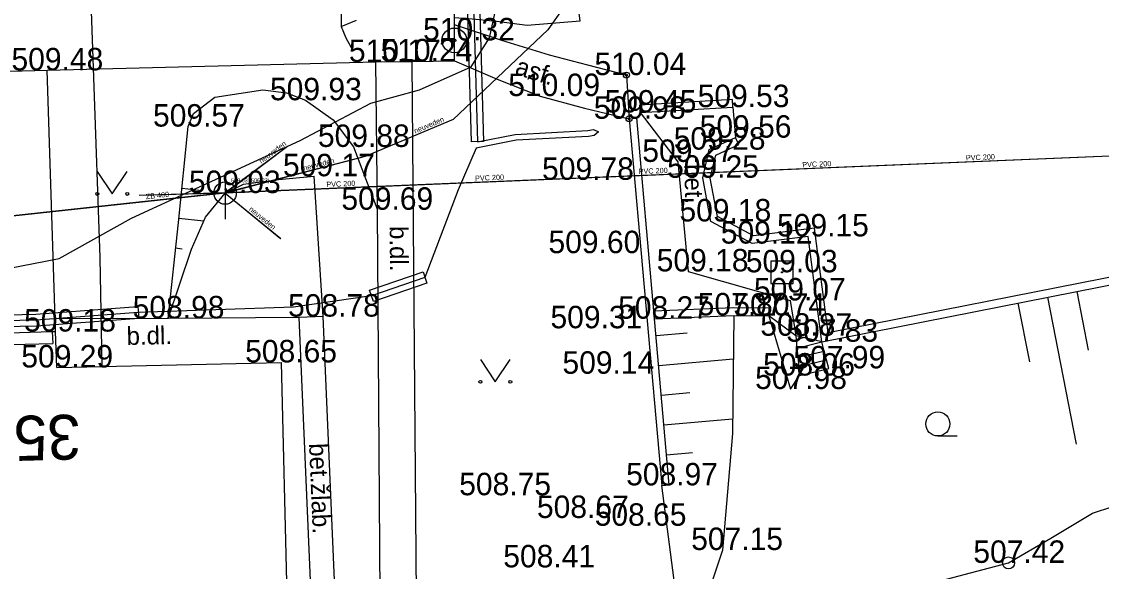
# Model space of a CAD drawing. Extents: x -669642 to -669119, y -1131006 to -1130466.
# Drawn here: x -669449.88 to -669413.8, y -1130563.48 to -1130545.11 of the extents above; entities that cross this region are included whole.
import ezdxf

# ---------------------------------------------------------------- set-up
doc = ezdxf.new("R2010")
doc.units = 0
for name, color, linetype in [('G_Bod_tecka', 7, 'Continuous'), ('G_Bod_vyska', 7, 'Continuous'), ('G_Bodove_pole', 7, 'Continuous'), ('G_Breh_Teren', 7, 'Continuous'), ('G_Budovy_Objekty', 7, 'Continuous'), ('G_Cesty_Schody', 7, 'Continuous'), ('G_Cisla_popisna', 7, 'Continuous'), ('G_Plochy_zpevnene', 7, 'Continuous'), ('G_Ploty', 7, 'Continuous'), ('G_Ploty_vstupy', 7, 'Continuous'), ('G_Popisy_povrchu', 7, 'Continuous'), ('G_Site-kanalizace', 7, 'Continuous'), ('G_Site-Sachty_N', 7, 'Continuous'), ('G_Site-Sloupy', 7, 'Continuous'), ('G_Vyskove_srafy', 7, 'Continuous'), ('G_Z_CHRANICKA-TEPLOVOD_kotovane', 7, 'Continuous'), ('G_Z_ELsilove_podz_kotovane', 7, 'Continuous'), ('G_Z_ELsilove_zrusene', 7, 'Continuous'), ('G_Z_KANAL_podz_kotovane', 7, 'Continuous'), ('G_Z_KANAL_podz_priblizne', 7, 'Continuous'), ('G_Z_PLYNY_podz_geodeticky', 7, 'Continuous'), ('G_Zelen-Znacky', 7, 'Continuous'), ('Vrstva 10', 7, 'Continuous'), ('Vrstva 12', 7, 'Continuous'), ('Vrstva 17', 7, 'Continuous'), ('Vrstva 2', 7, 'Continuous'), ('Vrstva 3', 7, 'Continuous'), ('Vrstva 8', 7, 'Continuous')]:
    doc.layers.add(name, color=color, linetype=linetype)

msp = doc.modelspace()

# ---------------------------------------------------------------- linework, layer by layer
at = {"layer": 'G_Bod_tecka'}
for p, q in [((-669435.42, -1130545.74), (-669435.42, -1130545.74)), ((-669438.04, -1130546.46), (-669438.04, -1130546.46)), ((-669436.84, -1130546.44), (-669436.84, -1130546.44)), ((-669449.03, -1130546.74), (-669449.03, -1130546.74)), ((-669429.67, -1130546.9), (-669429.67, -1130546.9)), ((-669432.55, -1130547.6), (-669432.55, -1130547.6)), ((-669440.39, -1130547.74), (-669440.39, -1130547.74)), ((-669426.11, -1130547.97), (-669426.11, -1130547.97)), ((-669429.58, -1130548.36), (-669429.58, -1130548.36)), ((-669429.21, -1130548.15), (-669429.21, -1130548.15)), ((-669444.31, -1130548.62), (-669444.31, -1130548.62)), ((-669426.02, -1130548.99), (-669426.02, -1130548.99)), ((-669438.79, -1130549.3), (-669438.79, -1130549.3)), ((-669426.9, -1130549.39), (-669426.9, -1130549.39)), ((-669427.95, -1130549.8), (-669427.95, -1130549.8)), ((-669440.1, -1130550.28), (-669440.1, -1130550.28)), ((-669431.3, -1130550.4), (-669431.3, -1130550.4)), ((-669427.12, -1130550.33), (-669427.12, -1130550.33)), ((-669443.08, -1130550.84), (-669443.08, -1130550.84)), ((-669437.99, -1130551.4), (-669437.99, -1130551.4)), ((-669426.85, -1130551.79), (-669426.85, -1130551.79)), ((-669423.6, -1130552.29), (-669423.6, -1130552.29)), ((-669425.47, -1130552.53), (-669425.47, -1130552.53)), ((-669431.05, -1130552.85), (-669431.05, -1130552.85)), ((-669427.61, -1130553.46), (-669427.61, -1130553.46)), ((-669424.47, -1130553.49), (-669424.47, -1130553.49)), ((-669424.2, -1130554.43), (-669424.2, -1130554.43)), ((-669444.98, -1130555.03), (-669444.98, -1130555.03)), ((-669439.8, -1130554.97), (-669439.8, -1130554.97)), ((-669428.76, -1130555.04), (-669428.76, -1130555.04)), ((-669426.08, -1130554.93), (-669426.08, -1130554.93)), ((-669424.91, -1130554.94), (-669424.91, -1130554.94)), ((-669448.75, -1130555.47), (-669448.75, -1130555.47)), ((-669431.08, -1130555.36), (-669431.08, -1130555.36)), ((-669424.01, -1130555.61), (-669424.01, -1130555.61)), ((-669423.14, -1130555.81), (-669423.14, -1130555.81)), ((-669448.7, -1130556.67), (-669448.7, -1130556.67)), ((-669441.21, -1130556.5), (-669441.21, -1130556.5)), ((-669422.91, -1130556.7), (-669422.91, -1130556.7)), ((-669430.76, -1130556.88), (-669430.76, -1130556.88)), ((-669423.88, -1130556.94), (-669423.88, -1130556.94)), ((-669424.19, -1130557.39), (-669424.19, -1130557.39)), ((-669428.49, -1130560.61), (-669428.49, -1130560.61)), ((-669434.07, -1130560.94), (-669434.07, -1130560.94)), ((-669431.46, -1130561.7), (-669431.46, -1130561.7)), ((-669429.53, -1130561.96), (-669429.53, -1130561.96)), ((-669426.46, -1130562.77), (-669426.46, -1130562.77)), ((-669416.9, -1130563.2), (-669416.9, -1130563.2)), ((-669432.66, -1130563.35), (-669432.66, -1130563.35))]:
    msp.add_line(p, q, dxfattribs=at)
at = {"layer": 'G_Bodove_pole'}
for radius in [0.412, 0.05]:
    msp.add_circle((-669435.42, -1130545.74), radius, dxfattribs=at)
at = {"layer": 'G_Breh_Teren'}
for p, q in [((-669439.8, -1130554.97), (-669440.1, -1130550.28)), ((-669424.01, -1130555.61), (-669424.91, -1130554.94)), ((-669424.91, -1130554.94), (-669424.19, -1130557.39)), ((-669424.19, -1130557.39), (-669423.88, -1130556.94))]:
    msp.add_line(p, q, dxfattribs=at)
for points in [[(-669444.98, -1130555.03), (-669444.64, -1130551.82), (-669444.31, -1130548.62), (-669444.14, -1130548.18), (-669443.42, -1130547.64), (-669441.82, -1130547.39), (-669441.03, -1130547.49), (-669440.39, -1130547.74), (-669439.47, -1130548.4), (-669438.79, -1130549.3), (-669438.39, -1130550.35), (-669437.99, -1130551.4)], [(-669444.98, -1130555.03), (-669444.2, -1130552.72), (-669443.74, -1130551.65), (-669443.08, -1130550.84), (-669442.46, -1130550.54), (-669441.3, -1130550.39), (-669440.1, -1130550.28)], [(-669426.08, -1130554.93), (-669426.12, -1130558.88), (-669426.46, -1130562.77), (-669427.04, -1130564.51), (-669427.76, -1130566.22)], [(-669427.76, -1130566.22), (-669425.46, -1130565.53), (-669423.17, -1130564.84), (-669420.03, -1130564.02), (-669416.9, -1130563.2), (-669415.49, -1130562.37), (-669414.09, -1130561.54), (-669413.41, -1130561.32), (-669412.72, -1130561.11)]]:
    msp.add_lwpolyline(points, dxfattribs=at)
at = {"layer": 'G_Budovy_Objekty'}
for p, q in [((-669452.25, -1130555.57), (-669448.86, -1130555.47)), ((-669448.86, -1130555.47), (-669448.84, -1130555.87)), ((-669448.86, -1130555.47), (-669448.75, -1130555.47)), ((-669448.7, -1130556.67), (-669448.75, -1130555.47)), ((-669452.24, -1130555.96), (-669448.84, -1130555.87)), ((-669448.7, -1130556.67), (-669441.21, -1130556.5)), ((-669441.21, -1130556.5), (-669440.93, -1130567.9))]:
    msp.add_line(p, q, dxfattribs=at)
at = {"layer": 'G_Cesty_Schody'}
for p, q in [((-669448.75, -1130555.47), (-669448.76, -1130555.05)), ((-669424.01, -1130555.61), (-669424, -1130555.73)), ((-669423.75, -1130555.67), (-669424.01, -1130555.61)), ((-669424, -1130555.73), (-669423.75, -1130555.67)), ((-669424, -1130555.73), (-669423.97, -1130556.03)), ((-669423.97, -1130556.03), (-669423.14, -1130555.81)), ((-669423.14, -1130555.81), (-669423.75, -1130555.67)), ((-669423.06, -1130556.12), (-669423.14, -1130555.81)), ((-669423.97, -1130556.03), (-669423.94, -1130556.33)), ((-669423.94, -1130556.33), (-669423.06, -1130556.12)), ((-669423.94, -1130556.33), (-669423.91, -1130556.64)), ((-669422.98, -1130556.41), (-669423.06, -1130556.12)), ((-669423.91, -1130556.64), (-669422.98, -1130556.41)), ((-669423.91, -1130556.64), (-669423.88, -1130556.94)), ((-669423.88, -1130556.94), (-669422.91, -1130556.7)), ((-669422.91, -1130556.7), (-669422.98, -1130556.41))]:
    msp.add_line(p, q, dxfattribs=at)
at = {"layer": 'G_Plochy_zpevnene'}
for p, q in [((-669435.41, -1130545.22), (-669435.4, -1130543.47)), ((-669435.41, -1130546.42), (-669435.41, -1130545.22)), ((-669449.03, -1130546.74), (-669438.04, -1130546.46)), ((-669438.04, -1130546.46), (-669436.84, -1130546.44)), ((-669437.99, -1130551.4), (-669438.04, -1130546.46)), ((-669436.84, -1130546.44), (-669435.41, -1130546.42)), ((-669436.84, -1130546.44), (-669436.65, -1130570.17)), ((-669452.43, -1130546.82), (-669449.03, -1130546.74)), ((-669448.76, -1130555.05), (-669449.03, -1130546.74)), ((-669426.12, -1130547.72), (-669429.22, -1130547.9)), ((-669429.21, -1130548.15), (-669429.22, -1130547.9)), ((-669429.21, -1130548.15), (-669426.11, -1130547.97)), ((-669426.11, -1130547.97), (-669426.12, -1130547.72)), ((-669426.11, -1130547.97), (-669426.02, -1130548.99)), ((-669426.9, -1130549.39), (-669426.02, -1130548.99)), ((-669425.91, -1130549.22), (-669426.02, -1130548.99)), ((-669427.12, -1130550.33), (-669426.9, -1130549.39)), ((-669426.68, -1130549.57), (-669425.91, -1130549.22)), ((-669426.87, -1130550.34), (-669426.68, -1130549.57)), ((-669426.85, -1130551.79), (-669427.12, -1130550.33)), ((-669426.63, -1130551.63), (-669426.87, -1130550.34)), ((-669437.86, -1130569.69), (-669437.99, -1130551.4)), ((-669425.42, -1130552.27), (-669426.63, -1130551.63)), ((-669425.47, -1130552.53), (-669426.85, -1130551.79)), ((-669423.38, -1130552.01), (-669425.42, -1130552.27)), ((-669422.93, -1130555.51), (-669423.38, -1130552.01)), ((-669423.6, -1130552.29), (-669425.47, -1130552.53)), ((-669423.14, -1130555.81), (-669423.6, -1130552.29)), ((-669409.64, -1130552.89), (-669422.93, -1130555.51)), ((-669427.61, -1130553.46), (-669424.2, -1130554.43)), ((-669423.14, -1130555.81), (-669409.59, -1130553.14)), ((-669424.2, -1130554.43), (-669424.01, -1130555.61)), ((-669426.09, -1130554.68), (-669428.75, -1130554.79)), ((-669424.91, -1130554.69), (-669426.09, -1130554.68)), ((-669424.91, -1130554.69), (-669424.91, -1130554.94)), ((-669428.73, -1130555.04), (-669426.08, -1130554.93)), ((-669426.08, -1130554.93), (-669424.91, -1130554.94))]:
    msp.add_line(p, q, dxfattribs=at)
for points in [[(-669429.67, -1130546.9), (-669430.96, -1130546.57), (-669432.24, -1130546.23), (-669433.83, -1130545.74), (-669435.41, -1130545.22)], [(-669435.41, -1130546.42), (-669433.99, -1130547.04), (-669432.55, -1130547.6), (-669431.07, -1130548), (-669429.58, -1130548.36)], [(-669429.21, -1130548.15), (-669427.95, -1130549.8), (-669427.61, -1130553.46)], [(-669440.6, -1130555), (-669444.98, -1130555.03), (-669448.76, -1130555.05)]]:
    msp.add_lwpolyline(points, dxfattribs=at)
at = {"layer": 'G_Ploty'}
for p, q in [((-669429.58, -1130548.36), (-669428.49, -1130560.61)), ((-669428.75, -1130554.79), (-669429.32, -1130548.33)), ((-669428.73, -1130555.04), (-669428.75, -1130554.79)), ((-669439.8, -1130554.97), (-669440.6, -1130555)), ((-669440.03, -1130568.46), (-669440.6, -1130555)), ((-669439.12, -1130570.88), (-669439.8, -1130554.97)), ((-669428.24, -1130560.59), (-669428.73, -1130555.04)), ((-669428.49, -1130560.61), (-669428.24, -1130560.59)), ((-669427.76, -1130566.22), (-669428.49, -1130560.61))]:
    msp.add_line(p, q, dxfattribs=at)
at = {"layer": 'G_Ploty_vstupy'}
msp.add_line((-669429.67, -1130546.9), (-669429.58, -1130548.36), dxfattribs=at)
at = {"layer": 'G_Site-kanalizace'}
msp.add_line((-669443.08, -1130550.465), (-669443.08, -1130551.715), dxfattribs=at)
msp.add_circle((-669443.08, -1130550.84), 0.375, dxfattribs=at)
at = {"layer": 'G_Site-Sachty_N'}
msp.add_lwpolyline([(-669424.845, -1130553.865), (-669424.095, -1130553.865), (-669424.095, -1130553.115), (-669424.845, -1130553.115)], close=True, dxfattribs=at)
msp.add_circle((-669424.47, -1130553.49), 0.02, dxfattribs=at)
at = {"layer": 'G_Site-Sloupy'}
for centre, radius in [((-669429.67, -1130546.9), 0.1), ((-669429.67, -1130546.9), 0.0348), ((-669429.58, -1130548.36), 0.1), ((-669429.58, -1130548.36), 0.0348), ((-669416.9, -1130563.2), 0.2)]:
    msp.add_circle(centre, radius, dxfattribs=at)
at = {"layer": 'G_Vyskove_srafy'}
for p, q in [((-669444.52, -1130550.68), (-669443.95, -1130550.74)), ((-669444.63, -1130551.68), (-669443.79, -1130551.77)), ((-669444.74, -1130552.67), (-669444.52, -1130552.7)), ((-669414.62, -1130554.13), (-669414.24, -1130556.09)), ((-669416.59, -1130554.52), (-669416.2, -1130556.48)), ((-669415.6, -1130554.32), (-669414.64, -1130559.23)), ((-669428.68, -1130555.6), (-669427.64, -1130555.51)), ((-669428.59, -1130556.6), (-669426.1, -1130556.38)), ((-669428.5, -1130557.6), (-669427.55, -1130557.51)), ((-669428.42, -1130558.59), (-669426.12, -1130558.39)), ((-669428.33, -1130559.59), (-669427.46, -1130559.51))]:
    msp.add_line(p, q, dxfattribs=at)
at = {"layer": 'G_Z_CHRANICKA-TEPLOVOD_kotovane'}
for points in [[(-669434.927, -1130532.245), (-669434.443, -1130549.123), (-669434.843, -1130549.135), (-669435.327, -1130532.257)], [(-669436.335, -1130553.849), (-669438.125, -1130554.469), (-669438.255, -1130554.091), (-669436.465, -1130553.471)], [(-669445.965, -1130555.029), (-669449.38, -1130555.29), (-669452.104, -1130555.349), (-669452.534, -1130555.499), (-669452.666, -1130555.121), (-669452.176, -1130554.951), (-669449.4, -1130554.89), (-669445.995, -1130554.631)]]:
    msp.add_lwpolyline(points, close=True, dxfattribs=at)
at = {"layer": 'G_Z_ELsilove_podz_kotovane'}
msp.add_lwpolyline([(-669435.127, -1130532.251), (-669434.721, -1130546.41), (-669434.643, -1130549.129), (-669433.382, -1130548.881), (-669430.96, -1130548.75), (-669430.772, -1130548.723), (-669430.6, -1130548.8), (-669430.744, -1130548.922), (-669430.94, -1130548.95), (-669433.358, -1130549.079), (-669434.688, -1130549.341), (-669435.29, -1130550.73), (-669436.4, -1130553.66), (-669438.19, -1130554.28), (-669440.79, -1130554.66), (-669445.98, -1130554.83), (-669449.39, -1130555.09), (-669452.14, -1130555.15)], dxfattribs=at)
at = {"layer": 'G_Z_ELsilove_zrusene'}
msp.add_lwpolyline([(-669452.329, -1130556.553), (-669452.332, -1130556.43), (-669452.675, -1130556.222), (-669452.959, -1130555.922), (-669452.945, -1130555.696), (-669452.844, -1130554.124), (-669452.528, -1130553.786), (-669448.62, -1130553.026), (-669446.206, -1130551.679), (-669440.57, -1130549.085), (-669438.209, -1130547.837), (-669436.586, -1130547.388), (-669434.856, -1130546.624), (-669434.721, -1130546.41), (-669434.242, -1130545.651), (-669433.821, -1130543.725)], dxfattribs=at)
msp.add_lwpolyline([(-669452.329, -1130556.553), (-669452.332, -1130556.43), (-669452.675, -1130556.222), (-669452.959, -1130555.922), (-669452.945, -1130555.696), (-669452.844, -1130554.124), (-669452.528, -1130553.786), (-669448.62, -1130553.026), (-669446.206, -1130551.679), (-669440.57, -1130549.085), (-669438.209, -1130547.837), (-669436.586, -1130547.388), (-669434.856, -1130546.624), (-669434.721, -1130546.41), (-669434.242, -1130545.651), (-669433.821, -1130543.725)], dxfattribs=at)
at = {"layer": 'G_Z_KANAL_podz_kotovane'}
for p, q in [((-669393.38, -1130548.77), (-669443.08, -1130550.84)), ((-669443.08, -1130550.84), (-669440.99, -1130549.28)), ((-669443.08, -1130550.84), (-669458.02, -1130552.46)), ((-669443.08, -1130550.84), (-669441.22, -1130552.36))]:
    msp.add_line(p, q, dxfattribs=at)
at = {"layer": 'G_Z_KANAL_podz_priblizne'}
msp.add_lwpolyline([(-669416.97, -1130528.54), (-669416.16, -1130528.77), (-669418.25, -1130540.62), (-669428.04, -1130541.96), (-669429.39, -1130542.16), (-669430.56, -1130542.9), (-669432.29, -1130545.39), (-669435.46, -1130548.38), (-669438.4, -1130549.62), (-669443.08, -1130550.84), (-669445.95, -1130550.92)], dxfattribs=at)
at = {"layer": 'G_Z_PLYNY_podz_geodeticky'}
for points in [[(-669441.37, -1130524.47), (-669439.2, -1130544.53), (-669439.2, -1130545.27), (-669439.05, -1130545.65), (-669438.81, -1130546.08)], [(-669448.11, -1130528.92), (-669447.27, -1130552.99), (-669447.2, -1130556.63)], [(-669435.437, -1130544.98), (-669434.94, -1130545.01), (-669434.01, -1130545.1), (-669432.99, -1130545.23), (-669431.21, -1130545.09), (-669431.34, -1130544.16), (-669431.41, -1130543.72)], [(-669439.2, -1130545.27), (-669438.69, -1130545.06)]]:
    msp.add_lwpolyline(points, dxfattribs=at)
at = {"layer": 'G_Zelen-Znacky'}
for p, q in [((-669447.35, -1130550.12), (-669446.85, -1130550.87)), ((-669446.85, -1130550.87), (-669446.35, -1130550.12)), ((-669434.55, -1130556.4), (-669434.05, -1130557.15)), ((-669434.05, -1130557.15), (-669433.55, -1130556.4)), ((-669419.262, -1130558.96), (-669418.612, -1130558.957))]:
    msp.add_line(p, q, dxfattribs=at)
for centre, radius in [((-669447.35, -1130550.87), 0.05), ((-669446.35, -1130550.87), 0.05), ((-669434.55, -1130557.15), 0.05), ((-669433.55, -1130557.15), 0.05), ((-669419.262, -1130558.557), 0.403)]:
    msp.add_circle(centre, radius, dxfattribs=at)
at = {"layer": 'Vrstva 10'}
msp.add_line((-669443.085, -1130550.836), (-669458.023, -1130552.455), dxfattribs=at)
at = {"layer": 'Vrstva 12'}
for p, q in [((-669393.38, -1130548.77), (-669443.085, -1130550.836)), ((-669443.085, -1130550.836), (-669440.992, -1130549.277)), ((-669443.085, -1130550.836), (-669441.223, -1130552.356))]:
    msp.add_line(p, q, dxfattribs=at)
at = {"layer": 'Vrstva 17'}
msp.add_lwpolyline([(-669416.97, -1130528.544), (-669416.157, -1130528.774), (-669418.249, -1130540.622), (-669428.042, -1130541.962), (-669429.385, -1130542.159), (-669430.555, -1130542.9), (-669432.295, -1130545.386), (-669435.463, -1130548.379), (-669438.403, -1130549.624), (-669443.085, -1130550.836), (-669445.949, -1130550.925)], dxfattribs=at)
msp.add_lwpolyline([(-669416.97, -1130528.544), (-669416.157, -1130528.774), (-669418.249, -1130540.622), (-669428.042, -1130541.962), (-669429.385, -1130542.159), (-669430.555, -1130542.9), (-669432.295, -1130545.386), (-669435.463, -1130548.379), (-669438.403, -1130549.624), (-669443.085, -1130550.836), (-669445.949, -1130550.925)], dxfattribs=at)
at = {"layer": 'Vrstva 8'}
msp.add_line((-669443.085, -1130550.836), (-669443.085, -1130550.836), dxfattribs=at)

# ---------------------------------------------------------------- texts
at = {"layer": 'G_Bod_vyska'}
for s, p in [('510.32', (-669436.464, -1130545.74)), ('510.17', (-669438.942, -1130546.46)), ('510.24', (-669437.884, -1130546.44)), ('509.48', (-669450.218, -1130546.74)), ('510.04', (-669430.736, -1130546.9)), ('509.93', (-669441.58, -1130547.74)), ('510.09', (-669433.618, -1130547.6)), ('509.53', (-669427.288, -1130547.97)), ('509.98', (-669430.76, -1130548.36)), ('509.45', (-669430.398, -1130548.15)), ('509.57', (-669445.488, -1130548.62)), ('509.56', (-669427.221, -1130548.99)), ('509.88', (-669439.978, -1130549.3)), ('509.28', (-669428.088, -1130549.39)), ('509.27', (-669429.138, -1130549.8)), ('509.17', (-669441.146, -1130550.28)), ('509.78', (-669432.488, -1130550.4)), ('509.25', (-669428.308, -1130550.33)), ('509.03', (-669444.289, -1130550.84)), ('509.69', (-669439.193, -1130551.4)), ('509.18', (-669427.896, -1130551.79)), ('509.15', (-669424.636, -1130552.29)), ('509.12', (-669426.516, -1130552.53)), ('509.60', (-669432.273, -1130552.85)), ('509.18', (-669428.656, -1130553.46)), ('509.03', (-669425.679, -1130553.49)), ('509.07', (-669425.409, -1130554.43)), ('507.80', (-669427.287, -1130554.93)), ('507.74', (-669426.096, -1130554.94)), ('508.98', (-669446.168, -1130555.03)), ('508.78', (-669440.976, -1130554.97)), ('508.27', (-669429.946, -1130555.04)), ('509.18', (-669449.796, -1130555.47)), ('509.31', (-669432.206, -1130555.36)), ('508.87', (-669425.196, -1130555.61)), ('507.83', (-669424.326, -1130555.81)), ('509.29', (-669449.89, -1130556.67)), ('508.65', (-669442.409, -1130556.5)), ('507.99', (-669424.09, -1130556.7)), ('509.14', (-669431.806, -1130556.88)), ('508.06', (-669425.101, -1130556.94)), ('507.98', (-669425.368, -1130557.39)), ('508.97', (-669429.678, -1130560.61)), ('508.75', (-669435.256, -1130560.94)), ('508.67', (-669432.659, -1130561.7)), ('508.65', (-669430.729, -1130561.96)), ('507.15', (-669427.504, -1130562.77)), ('507.42', (-669418.076, -1130563.2)), ('508.41', (-669433.784, -1130563.35))]:
    msp.add_text(s, height=0.75, dxfattribs=at).set_placement(p)
at = {"layer": 'G_Cisla_popisna'}
msp.add_text('3501', height=1.5, rotation=181.5776, dxfattribs=at).set_placement((-669447.928, -1130558.236))
at = {"layer": 'G_Popisy_povrchu'}
for s, rotation, p in [('asf.', 342.4168, (-669433.424, -1130546.858)), ('bet.', 271.384, (-669427.735, -1130549.881)), ('b.dl.', 270.3978, (-669437.579, -1130551.945)), ('b.dl.', 1.3308, (-669446.365, -1130555.92)), ('bet.žlab.', 272.4194, (-669440.275, -1130559.212))]:
    msp.add_text(s, height=0.6, rotation=rotation, dxfattribs=at).set_placement(p)
at = {"layer": 'Vrstva 2'}
msp.add_text('509.03 (506.23)', height=0.13163, dxfattribs=at).set_placement((-669442.879, -1130550.483))
at = {"layer": 'Vrstva 3'}
for s, rotation, p in [('neuveden', 22.9373, (-669436.724, -1130548.856)), ('neuveden', 36.6591, (-669441.868, -1130549.864)), ('neuveden', 14.5119, (-669440.445, -1130550.098)), ('PVC 200', 2.3789, (-669423.789, -1130549.981)), ('PVC 200', 2.3633, (-669418.322, -1130549.754)), ('PVC 200', 2.3789, (-669434.724, -1130550.435)), ('PVC 200', 2.3803, (-669429.256, -1130550.208)), ('PVC 200', 2.3647, (-669439.694, -1130550.642)), ('ZB 400', 6.1789, (-669445.719, -1130551.05)), ('neuveden', 320.757, (-669442.299, -1130551.408))]:
    msp.add_text(s, height=0.1755, rotation=rotation, dxfattribs=at).set_placement(p)

doc.saveas('drawing.dxf')
